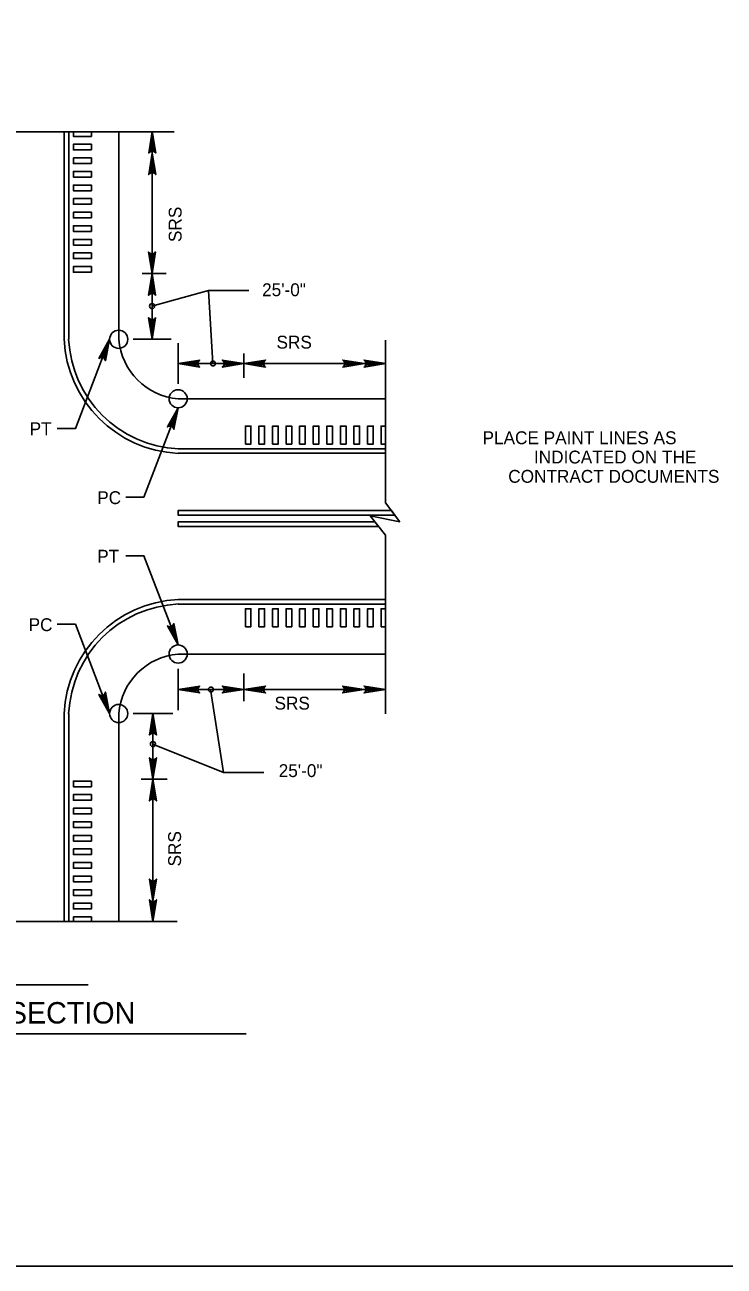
# Model space of a CAD drawing. Extents: x 632008 to 634206, y 294231 to 297795.
# Drawn here: x 632215 to 632378.2, y 296621.6 to 296911.1 of the extents above; entities that cross this region are included whole.
import ezdxf

# ---------------------------------------------------------------- set-up
doc = ezdxf.new("R2010")
doc.units = 0
doc.layers.add('1', color=7, linetype='Continuous')
doc.layers.add('Level 2', color=7, linetype='Continuous')

msp = doc.modelspace()

# ---------------------------------------------------------------- linework, layer by layer
at = {"layer": '1'}
for p, q in [((632178.07, 296687.2), (632229.83, 296687.2)), ((632143.19, 296675.83), (632266.7, 296675.83))]:
    msp.add_line(p, q, dxfattribs=at)
msp.add_lwpolyline([(632833.86, 296621.62), (632833.86, 297185.62), (632047.86, 297185.62), (632047.86, 296621.62), (632833.86, 296621.62), (632833.86, 296647.98), (632633.86, 296647.98), (632633.86, 296712.66), (632833.86, 296712.66), (632833.86, 296741.62), (632633.86, 296741.62), (632633.86, 296621.62), (632712.66, 296621.62), (632712.66, 296647.98), (632712.66, 296621.62), (632789.66, 296621.62), (632789.66, 296647.98), (632789.66, 296635.66), (632833.86, 296635.66)], dxfattribs=at)
for points in [[(632301.38, 296796.77), (632250.81, 296796.77), (632250.81, 296797.83), (632300.59, 296797.83)], [(632297.54, 296794.13), (632250.81, 296794.13), (632250.81, 296795.19), (632296.68, 296795.19)]]:
    msp.add_lwpolyline(points, close=True, dxfattribs=at)
at = {"layer": 'Level 2'}
for p, q in [((632249.9, 296886.16), (632212.7, 296886.16)), ((632224.24, 296837.78), (632224.24, 296886.16)), ((632225.29, 296837.78), (632225.29, 296886.16)), ((632236.94, 296837.78), (632236.94, 296886.16)), ((632244.73, 296837.78), (632244.73, 296886.16)), ((632248.04, 296853.11), (632242.38, 296853.11)), ((632257.89, 296849.15), (632244.67, 296845.49)), ((632249.17, 296837.78), (632240.29, 296837.78)), ((632250.81, 296827.36), (632250.81, 296836.91)), ((632299.21, 296799.66), (632299.21, 296837.6)), ((632266.15, 296828.83), (632266.15, 296834.44)), ((632250.81, 296832.14), (632299.21, 296832.14)), ((632299.21, 296823.91), (632250.81, 296823.91)), ((632299.21, 296812.26), (632250.81, 296812.26)), ((632299.21, 296811.2), (632250.81, 296811.2)), ((632302.53, 296795.23), (632299.21, 296799.66)), ((632299.21, 296792.08), (632295.56, 296796.58)), ((632295.56, 296796.58), (632302.53, 296795.23)), ((632299.21, 296750.44), (632299.21, 296792.08)), ((632299.21, 296777.08), (632250.81, 296777.08)), ((632299.21, 296776.03), (632250.81, 296776.03)), ((632299.21, 296764.38), (632250.81, 296764.38)), ((632250.81, 296751.3), (632250.81, 296760.95)), ((632266.15, 296753.42), (632266.15, 296759.85)), ((632250.81, 296756.12), (632299.21, 296756.12)), ((632261.37, 296736.77), (632258.39, 296756.14)), ((632224.24, 296702.03), (632224.24, 296750.51)), ((632225.29, 296702.03), (632225.29, 296750.51)), ((632236.94, 296702.03), (632236.94, 296750.51)), ((632249.54, 296750.51), (632240.34, 296750.51)), ((632244.94, 296750.51), (632244.94, 296702.03)), ((632248.24, 296735.17), (632242.18, 296735.17)), ((632250.58, 296702.03), (632212.7, 296702.03))]:
    msp.add_line(p, q, dxfattribs=at)
for points in [[(632226.37, 296886.16), (632226.37, 296885.1), (632230.59, 296885.1), (632230.59, 296886.16)], [(632245.37, 296881.44), (632245.02, 296881.62), (632244.76, 296886.24), (632245.37, 296881.44), (632245.58, 296881.2), (632244.76, 296886.24), (632244.54, 296881.63), (632244.2, 296881.46), (632244.76, 296886.24), (632243.96, 296881.2), (632244.2, 296881.46)], [(632245.37, 296876.42), (632245.02, 296876.6), (632244.76, 296881.22), (632245.37, 296876.42), (632245.58, 296876.18), (632244.76, 296881.22), (632244.54, 296876.61), (632244.2, 296876.44), (632244.76, 296881.22), (632243.96, 296876.18), (632244.2, 296876.44)], [(632245.34, 296857.91), (632244.99, 296857.73), (632244.73, 296853.11), (632245.34, 296857.91), (632245.55, 296858.15), (632244.73, 296853.11), (632244.51, 296857.73), (632244.17, 296857.9), (632244.73, 296853.11), (632243.93, 296858.15), (632244.17, 296857.9)], [(632245.34, 296848.32), (632244.99, 296848.5), (632244.73, 296853.11), (632245.34, 296848.32), (632245.55, 296848.07), (632244.73, 296853.11), (632244.51, 296848.5), (632244.17, 296848.33), (632244.73, 296853.11), (632243.93, 296848.07), (632244.17, 296848.33)], [(632267.3, 296849.15), (632257.89, 296849.15), (632258.93, 296832.1)], [(632245.34, 296842.57), (632244.99, 296842.39), (632244.73, 296837.78), (632245.34, 296842.57), (632245.55, 296842.82), (632244.73, 296837.78), (632244.51, 296842.39), (632244.17, 296842.56), (632244.73, 296837.78), (632243.93, 296842.82), (632244.17, 296842.56)], [(632222.62, 296816.97), (632226.84, 296816.97), (632234.83, 296837.78)], [(632232.6, 296833.49), (632232.98, 296833.54), (632234.83, 296837.78), (632232.6, 296833.49), (632232.31, 296833.33), (632234.83, 296837.78), (632233.44, 296833.37), (632233.7, 296833.1), (632234.83, 296837.78), (632233.83, 296832.77), (632233.7, 296833.1)], [(632255.61, 296831.53), (632255.43, 296831.88), (632250.81, 296832.14), (632255.61, 296831.53), (632255.85, 296831.32), (632250.81, 296832.14), (632255.43, 296832.36), (632255.6, 296832.7), (632250.81, 296832.14), (632255.85, 296832.94), (632255.6, 296832.7)], [(632261.36, 296831.53), (632261.53, 296831.88), (632266.15, 296832.14), (632261.36, 296831.53), (632261.11, 296831.32), (632266.15, 296832.14), (632261.54, 296832.36), (632261.37, 296832.7), (632266.15, 296832.14), (632261.11, 296832.94), (632261.37, 296832.7)], [(632270.95, 296831.53), (632270.77, 296831.88), (632266.15, 296832.14), (632270.95, 296831.53), (632271.19, 296831.32), (632266.15, 296832.14), (632270.76, 296832.36), (632270.93, 296832.7), (632266.15, 296832.14), (632271.19, 296832.94), (632270.93, 296832.7)], [(632289.47, 296831.53), (632289.65, 296831.87), (632294.26, 296832.13), (632289.47, 296831.53), (632289.22, 296831.32), (632294.26, 296832.13), (632289.65, 296832.36), (632289.48, 296832.7), (632294.26, 296832.13), (632289.22, 296832.93), (632289.48, 296832.7)], [(632294.43, 296831.53), (632294.61, 296831.87), (632299.23, 296832.13), (632294.43, 296831.53), (632294.19, 296831.32), (632299.23, 296832.13), (632294.62, 296832.36), (632294.45, 296832.7), (632299.23, 296832.13), (632294.19, 296832.93), (632294.45, 296832.7)], [(632238.6, 296800.99), (632242.82, 296800.99), (632250.81, 296821.8)], [(632248.58, 296817.51), (632248.96, 296817.56), (632250.81, 296821.8), (632248.58, 296817.51), (632248.29, 296817.35), (632250.81, 296821.8), (632249.42, 296817.39), (632249.68, 296817.12), (632250.81, 296821.8), (632249.81, 296816.79), (632249.68, 296817.12)], [(632299.21, 296817.55), (632298.15, 296817.55), (632298.15, 296813.33), (632299.21, 296813.33)], [(632238.6, 296787.3), (632242.82, 296787.3), (632250.81, 296766.49)], [(632299.21, 296774.95), (632298.15, 296774.95), (632298.15, 296770.73), (632299.21, 296770.73)], [(632222.62, 296771.32), (632226.84, 296771.32), (632234.83, 296750.51)], [(632248.58, 296770.77), (632248.96, 296770.73), (632250.81, 296766.49), (632248.58, 296770.77), (632248.29, 296770.93), (632250.81, 296766.49), (632249.42, 296770.89), (632249.68, 296771.17), (632250.81, 296766.49), (632249.81, 296771.49), (632249.68, 296771.17)], [(632232.6, 296754.79), (632232.98, 296754.75), (632234.83, 296750.51), (632232.6, 296754.79), (632232.31, 296754.95), (632234.83, 296750.51), (632233.44, 296754.91), (632233.7, 296755.19), (632234.83, 296750.51), (632233.83, 296755.51), (632233.7, 296755.19)], [(632255.61, 296755.52), (632255.43, 296755.87), (632250.81, 296756.12), (632255.61, 296755.52), (632255.85, 296755.31), (632250.81, 296756.12), (632255.43, 296756.35), (632255.6, 296756.69), (632250.81, 296756.12), (632255.85, 296756.92), (632255.6, 296756.69)], [(632261.36, 296755.52), (632261.53, 296755.87), (632266.15, 296756.12), (632261.36, 296755.52), (632261.11, 296755.31), (632266.15, 296756.12), (632261.54, 296756.35), (632261.37, 296756.69), (632266.15, 296756.12), (632261.11, 296756.92), (632261.37, 296756.69)], [(632270.95, 296755.52), (632270.77, 296755.87), (632266.15, 296756.12), (632270.95, 296755.52), (632271.19, 296755.31), (632266.15, 296756.12), (632270.76, 296756.35), (632270.93, 296756.69), (632266.15, 296756.12), (632271.19, 296756.92), (632270.93, 296756.69)], [(632289.4, 296755.52), (632289.57, 296755.87), (632294.19, 296756.12), (632289.4, 296755.52), (632289.15, 296755.31), (632294.19, 296756.12), (632289.58, 296756.35), (632289.41, 296756.69), (632294.19, 296756.12), (632289.15, 296756.92), (632289.41, 296756.69)], [(632294.42, 296755.52), (632294.59, 296755.87), (632299.21, 296756.12), (632294.42, 296755.52), (632294.17, 296755.31), (632299.21, 296756.12), (632294.6, 296756.35), (632294.43, 296756.69), (632299.21, 296756.12), (632294.17, 296756.92), (632294.43, 296756.69)], [(632245.54, 296745.71), (632245.19, 296745.89), (632244.94, 296750.51), (632245.54, 296745.71), (632245.75, 296745.47), (632244.94, 296750.51), (632244.71, 296745.89), (632244.37, 296745.72), (632244.94, 296750.51), (632244.14, 296745.47), (632244.37, 296745.72)], [(632270.78, 296736.77), (632261.37, 296736.77), (632244.89, 296743.33)], [(632245.54, 296739.96), (632245.19, 296739.79), (632244.94, 296735.17), (632245.54, 296739.96), (632245.75, 296740.21), (632244.94, 296735.17), (632244.71, 296739.78), (632244.37, 296739.95), (632244.94, 296735.17), (632244.14, 296740.21), (632244.37, 296739.95)], [(632245.54, 296730.37), (632245.19, 296730.55), (632244.94, 296735.17), (632245.54, 296730.37), (632245.75, 296730.13), (632244.94, 296735.17), (632244.71, 296730.56), (632244.37, 296730.39), (632244.94, 296735.17), (632244.14, 296730.13), (632244.37, 296730.39)], [(632245.55, 296711.63), (632245.2, 296711.45), (632244.94, 296706.84), (632245.55, 296711.63), (632245.75, 296711.88), (632244.94, 296706.84), (632244.71, 296711.45), (632244.37, 296711.62), (632244.94, 296706.84), (632244.14, 296711.88), (632244.37, 296711.62)], [(632245.55, 296706.82), (632245.2, 296706.65), (632244.94, 296702.03), (632245.55, 296706.82), (632245.75, 296707.07), (632244.94, 296702.03), (632244.71, 296706.64), (632244.37, 296706.81), (632244.94, 296702.03), (632244.14, 296707.07), (632244.37, 296706.81)], [(632226.37, 296702.03), (632226.37, 296703.09), (632230.59, 296703.09), (632230.59, 296702.03)]]:
    msp.add_lwpolyline(points, dxfattribs=at)
for points in [[(632230.59, 296881.94), (632230.59, 296883.26), (632226.37, 296883.26), (632226.37, 296881.94)], [(632230.59, 296878.77), (632230.59, 296880.09), (632226.37, 296880.09), (632226.37, 296878.77)], [(632230.59, 296875.6), (632230.59, 296876.92), (632226.37, 296876.92), (632226.37, 296875.6)], [(632230.59, 296872.43), (632230.59, 296873.75), (632226.37, 296873.75), (632226.37, 296872.43)], [(632230.59, 296869.27), (632230.59, 296870.59), (632226.37, 296870.59), (632226.37, 296869.27)], [(632230.59, 296866.1), (632230.59, 296867.42), (632226.37, 296867.42), (632226.37, 296866.1)], [(632230.59, 296862.93), (632230.59, 296864.25), (632226.37, 296864.25), (632226.37, 296862.93)], [(632230.59, 296859.77), (632230.59, 296861.09), (632226.37, 296861.09), (632226.37, 296859.77)], [(632230.59, 296856.6), (632230.59, 296857.92), (632226.37, 296857.92), (632226.37, 296856.6)], [(632230.59, 296853.43), (632230.59, 296854.75), (632226.37, 296854.75), (632226.37, 296853.43)], [(632266.48, 296813.33), (632267.8, 296813.33), (632267.8, 296817.55), (632266.48, 296817.55)], [(632269.65, 296813.33), (632270.97, 296813.33), (632270.97, 296817.55), (632269.65, 296817.55)], [(632272.82, 296813.33), (632274.14, 296813.33), (632274.14, 296817.55), (632272.82, 296817.55)], [(632275.99, 296813.33), (632277.3, 296813.33), (632277.3, 296817.55), (632275.99, 296817.55)], [(632279.15, 296813.33), (632280.47, 296813.33), (632280.47, 296817.55), (632279.15, 296817.55)], [(632282.32, 296813.33), (632283.64, 296813.33), (632283.64, 296817.55), (632282.32, 296817.55)], [(632285.49, 296813.33), (632286.81, 296813.33), (632286.81, 296817.55), (632285.49, 296817.55)], [(632288.65, 296813.33), (632289.97, 296813.33), (632289.97, 296817.55), (632288.65, 296817.55)], [(632291.82, 296813.33), (632293.14, 296813.33), (632293.14, 296817.55), (632291.82, 296817.55)], [(632294.99, 296813.33), (632296.31, 296813.33), (632296.31, 296817.55), (632294.99, 296817.55)], [(632266.48, 296770.73), (632267.8, 296770.73), (632267.8, 296774.95), (632266.48, 296774.95)], [(632269.65, 296770.73), (632270.97, 296770.73), (632270.97, 296774.95), (632269.65, 296774.95)], [(632272.82, 296770.73), (632274.14, 296770.73), (632274.14, 296774.95), (632272.82, 296774.95)], [(632275.98, 296770.73), (632277.3, 296770.73), (632277.3, 296774.95), (632275.98, 296774.95)], [(632279.15, 296770.73), (632280.47, 296770.73), (632280.47, 296774.95), (632279.15, 296774.95)], [(632282.32, 296770.73), (632283.64, 296770.73), (632283.64, 296774.95), (632282.32, 296774.95)], [(632285.48, 296770.73), (632286.8, 296770.73), (632286.8, 296774.95), (632285.48, 296774.95)], [(632288.65, 296770.73), (632289.97, 296770.73), (632289.97, 296774.95), (632288.65, 296774.95)], [(632291.82, 296770.73), (632293.14, 296770.73), (632293.14, 296774.95), (632291.82, 296774.95)], [(632294.99, 296770.73), (632296.3, 296770.73), (632296.3, 296774.95), (632294.99, 296774.95)], [(632230.59, 296734.76), (632230.59, 296733.44), (632226.37, 296733.44), (632226.37, 296734.76)], [(632230.59, 296731.59), (632230.59, 296730.27), (632226.37, 296730.27), (632226.37, 296731.59)], [(632230.59, 296728.42), (632230.59, 296727.1), (632226.37, 296727.1), (632226.37, 296728.42)], [(632230.59, 296725.26), (632230.59, 296723.94), (632226.37, 296723.94), (632226.37, 296725.26)], [(632230.59, 296722.09), (632230.59, 296720.77), (632226.37, 296720.77), (632226.37, 296722.09)], [(632230.59, 296718.92), (632230.59, 296717.6), (632226.37, 296717.6), (632226.37, 296718.92)], [(632230.59, 296715.75), (632230.59, 296714.44), (632226.37, 296714.44), (632226.37, 296715.75)], [(632230.59, 296712.59), (632230.59, 296711.27), (632226.37, 296711.27), (632226.37, 296712.59)], [(632230.59, 296709.42), (632230.59, 296708.1), (632226.37, 296708.1), (632226.37, 296709.42)], [(632230.59, 296706.25), (632230.59, 296704.93), (632226.37, 296704.93), (632226.37, 296706.25)]]:
    msp.add_lwpolyline(points, close=True, dxfattribs=at)
for centre, radius in [((632244.73, 296845.53), 0.581), ((632236.94, 296837.78), 2.11), ((632258.94, 296832.14), 0.581), ((632250.81, 296823.91), 2.11), ((632250.81, 296764.38), 2.11), ((632258.45, 296756.11), 0.581), ((632236.94, 296750.51), 2.11), ((632244.93, 296743.38), 0.581)]:
    msp.add_circle(centre, radius, dxfattribs=at)
for centre, radius, start, end in [((632252.1, 296839.06), 27.91, 182.6354, 267.3646), ((632252.1, 296839.06), 26.86, 182.6354, 267.3646), ((632252.1, 296839.06), 15.21, 184.837, 265.163), ((632252.1, 296749.22), 27.91, 92.6354, 177.3646), ((632252.1, 296749.22), 26.86, 92.6354, 177.3646), ((632252.1, 296749.22), 15.21, 94.837, 175.163)]:
    msp.add_arc(centre, radius, start, end, dxfattribs=at)

# ---------------------------------------------------------------- texts
for p in [(632251.61, 296860.46), (632251.49, 296714.84)]:
    msp.add_text('SRS', height=3, rotation=90, dxfattribs=at).set_placement(p)
for s, height, p in [('25\'-0"', 3, (632270.39, 296847.84)), ('SRS', 3, (632273.75, 296835.62)), ('PT', 3, (632216.17, 296815.42)), ('PLACE PAINT LINES AS', 3, (632321.8, 296813.32)), ('INDICATED ON THE', 3, (632333.8, 296808.82)), ('CONTRACT DOCUMENTS', 3, (632327.8, 296804.32)), ('PC', 3, (632231.93, 296799.35)), ('PT', 3, (632231.93, 296785.69)), ('PC', 3, (632215.93, 296769.72)), ('SRS', 3, (632273.29, 296751.43)), ('25\'-0"', 3, (632274.26, 296735.69)), ('SRS TYPICAL INTERSECTION', 5, (632145.7, 296678.21))]:
    msp.add_text(s, height=height, dxfattribs=at).set_placement(p)

doc.saveas('drawing.dxf')
